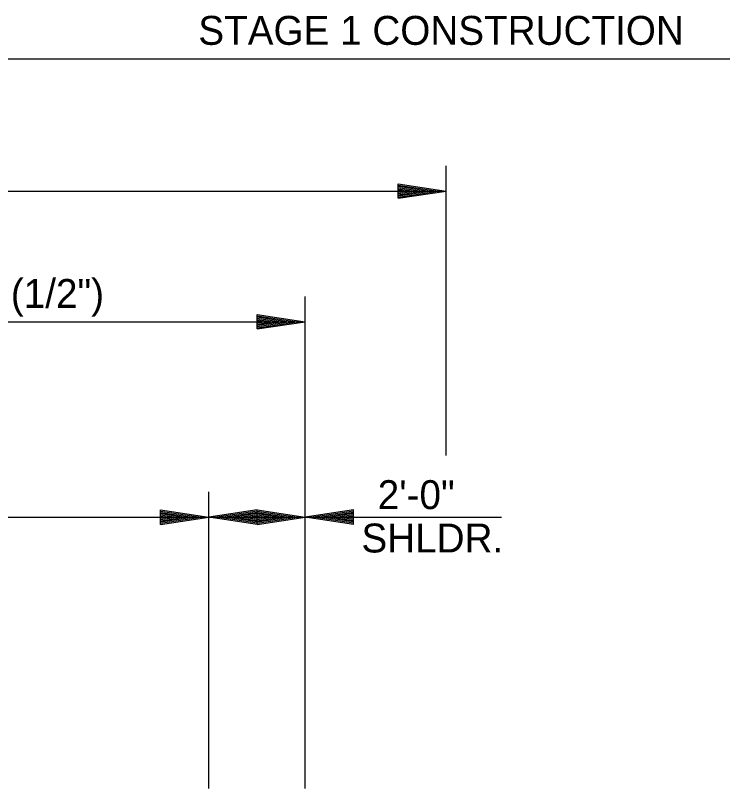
# Model space of a CAD drawing. Extents: x 2829243 to 2838161, y 467639 to 474695.
# Drawn here: x 2830585.4 to 2830732.2, y 467813.3 to 467973.7 of the extents above; entities that cross this region are included whole.
import ezdxf

# ---------------------------------------------------------------- set-up
doc = ezdxf.new("R2010")
doc.units = 0
doc.layers.add('R_Dimension', color=7, linetype='Continuous')
doc.layers.add('R_Draft', color=7, linetype='Continuous')

msp = doc.modelspace()

# ---------------------------------------------------------------- linework, layer by layer
at = {"layer": 'R_Dimension'}
for p, q in [((2830957.27, 467964.63), (2830390.54, 467964.63)), ((2830674.83, 467882.4), (2830674.83, 467942.53)), ((2830664.83, 467938.78), (2830674.83, 467937.28)), ((2830664.83, 467935.78), (2830664.83, 467938.78)), ((2830664.83, 467938.53), (2830673.16, 467937.28)), ((2830409.61, 467937.28), (2830674.83, 467937.28)), ((2830664.83, 467938.27), (2830671.44, 467937.28)), ((2830664.83, 467938.02), (2830669.77, 467937.28)), ((2830664.83, 467937.77), (2830668.08, 467937.28)), ((2830664.83, 467937.51), (2830666.41, 467937.28)), ((2830664.83, 467935.78), (2830674.83, 467937.28)), ((2830664.83, 467936.79), (2830668.08, 467937.28)), ((2830664.83, 467936.28), (2830671.44, 467937.28)), ((2830664.83, 467936.03), (2830673.16, 467937.28)), ((2830664.83, 467936.53), (2830669.77, 467937.28)), ((2830664.83, 467937.04), (2830666.41, 467937.28)), ((2830645.56, 467813.29), (2830645.56, 467915.43)), ((2830635.56, 467911.67), (2830645.56, 467910.17)), ((2830635.56, 467908.67), (2830635.56, 467911.67)), ((2830635.56, 467911.42), (2830643.89, 467910.17)), ((2830635.56, 467911.17), (2830642.17, 467910.17)), ((2830435.56, 467910.17), (2830645.56, 467910.17)), ((2830635.56, 467910.92), (2830640.51, 467910.17)), ((2830635.56, 467910.66), (2830638.81, 467910.17)), ((2830635.56, 467910.41), (2830637.14, 467910.17)), ((2830635.56, 467908.67), (2830645.56, 467910.17)), ((2830635.56, 467909.69), (2830638.81, 467910.17)), ((2830635.56, 467909.18), (2830642.17, 467910.17)), ((2830635.56, 467908.92), (2830643.89, 467910.17)), ((2830635.56, 467909.43), (2830640.51, 467910.17)), ((2830635.56, 467909.94), (2830637.14, 467910.17)), ((2830625.56, 467813.29), (2830625.56, 467874.86)), ((2830615.56, 467871.11), (2830625.56, 467869.61)), ((2830615.56, 467868.11), (2830615.56, 467871.11)), ((2830635.56, 467871.11), (2830625.56, 467869.61)), ((2830635.56, 467868.11), (2830635.56, 467871.11)), ((2830635.56, 467871.11), (2830645.56, 467869.61)), ((2830635.56, 467868.11), (2830635.56, 467871.11)), ((2830655.56, 467871.11), (2830645.56, 467869.61)), ((2830655.56, 467868.11), (2830655.56, 467871.11)), ((2830475.56, 467869.61), (2830625.56, 467869.61)), ((2830615.56, 467870.86), (2830623.89, 467869.61)), ((2830615.56, 467870.6), (2830622.17, 467869.61)), ((2830615.56, 467870.35), (2830620.51, 467869.61)), ((2830615.56, 467870.1), (2830618.81, 467869.61)), ((2830615.56, 467869.84), (2830617.14, 467869.61)), ((2830615.56, 467868.11), (2830625.56, 467869.61)), ((2830615.56, 467869.12), (2830618.81, 467869.61)), ((2830615.56, 467868.61), (2830622.17, 467869.61)), ((2830615.56, 467868.36), (2830623.89, 467869.61)), ((2830615.56, 467868.86), (2830620.51, 467869.61)), ((2830615.56, 467869.37), (2830617.14, 467869.61)), ((2830625.56, 467869.61), (2830686.32, 467869.61)), ((2830635.56, 467868.11), (2830625.56, 467869.61)), ((2830635.56, 467870.86), (2830627.23, 467869.61)), ((2830635.56, 467868.36), (2830627.23, 467869.61)), ((2830635.56, 467870.6), (2830628.95, 467869.61)), ((2830635.56, 467868.61), (2830628.95, 467869.61)), ((2830635.56, 467870.35), (2830630.62, 467869.61)), ((2830635.56, 467868.86), (2830630.62, 467869.61)), ((2830635.56, 467870.1), (2830632.31, 467869.61)), ((2830635.56, 467869.12), (2830632.31, 467869.61)), ((2830635.56, 467869.84), (2830633.98, 467869.61)), ((2830635.56, 467869.37), (2830633.98, 467869.61)), ((2830635.56, 467870.86), (2830643.89, 467869.61)), ((2830635.56, 467870.6), (2830642.17, 467869.61)), ((2830635.56, 467870.35), (2830640.51, 467869.61)), ((2830635.56, 467870.1), (2830638.81, 467869.61)), ((2830635.56, 467869.84), (2830637.14, 467869.61)), ((2830635.56, 467868.11), (2830645.56, 467869.61)), ((2830635.56, 467869.12), (2830638.81, 467869.61)), ((2830635.56, 467868.61), (2830642.17, 467869.61)), ((2830635.56, 467868.36), (2830643.89, 467869.61)), ((2830635.56, 467868.86), (2830640.51, 467869.61)), ((2830635.56, 467869.37), (2830637.14, 467869.61)), ((2830655.56, 467868.11), (2830645.56, 467869.61)), ((2830655.56, 467870.86), (2830647.23, 467869.61)), ((2830655.56, 467868.36), (2830647.23, 467869.61)), ((2830655.56, 467870.6), (2830648.95, 467869.61)), ((2830655.56, 467868.61), (2830648.95, 467869.61)), ((2830655.56, 467870.35), (2830650.62, 467869.61)), ((2830655.56, 467868.86), (2830650.62, 467869.61)), ((2830655.56, 467870.1), (2830652.31, 467869.61)), ((2830655.56, 467869.12), (2830652.31, 467869.61)), ((2830655.56, 467869.84), (2830653.98, 467869.61)), ((2830655.56, 467869.37), (2830653.98, 467869.61))]:
    msp.add_line(p, q, dxfattribs=at)

# ---------------------------------------------------------------- texts
for s, p in [('STAGE 1 CONSTRUCTION', (2830623.38, 467967.63)), ('2\'-0"', (2830660.61, 467871.28)), ('SHLDR.', (2830657.23, 467862.28))]:
    msp.add_text(s, height=6, dxfattribs=at).set_placement(p)
at = {"layer": 'R_Draft'}
msp.add_text('21\'-0" ACHM SURFACE COURSE (1/2")', height=6, dxfattribs=at).set_placement((2830458.83, 467913.03))

doc.saveas('drawing.dxf')
